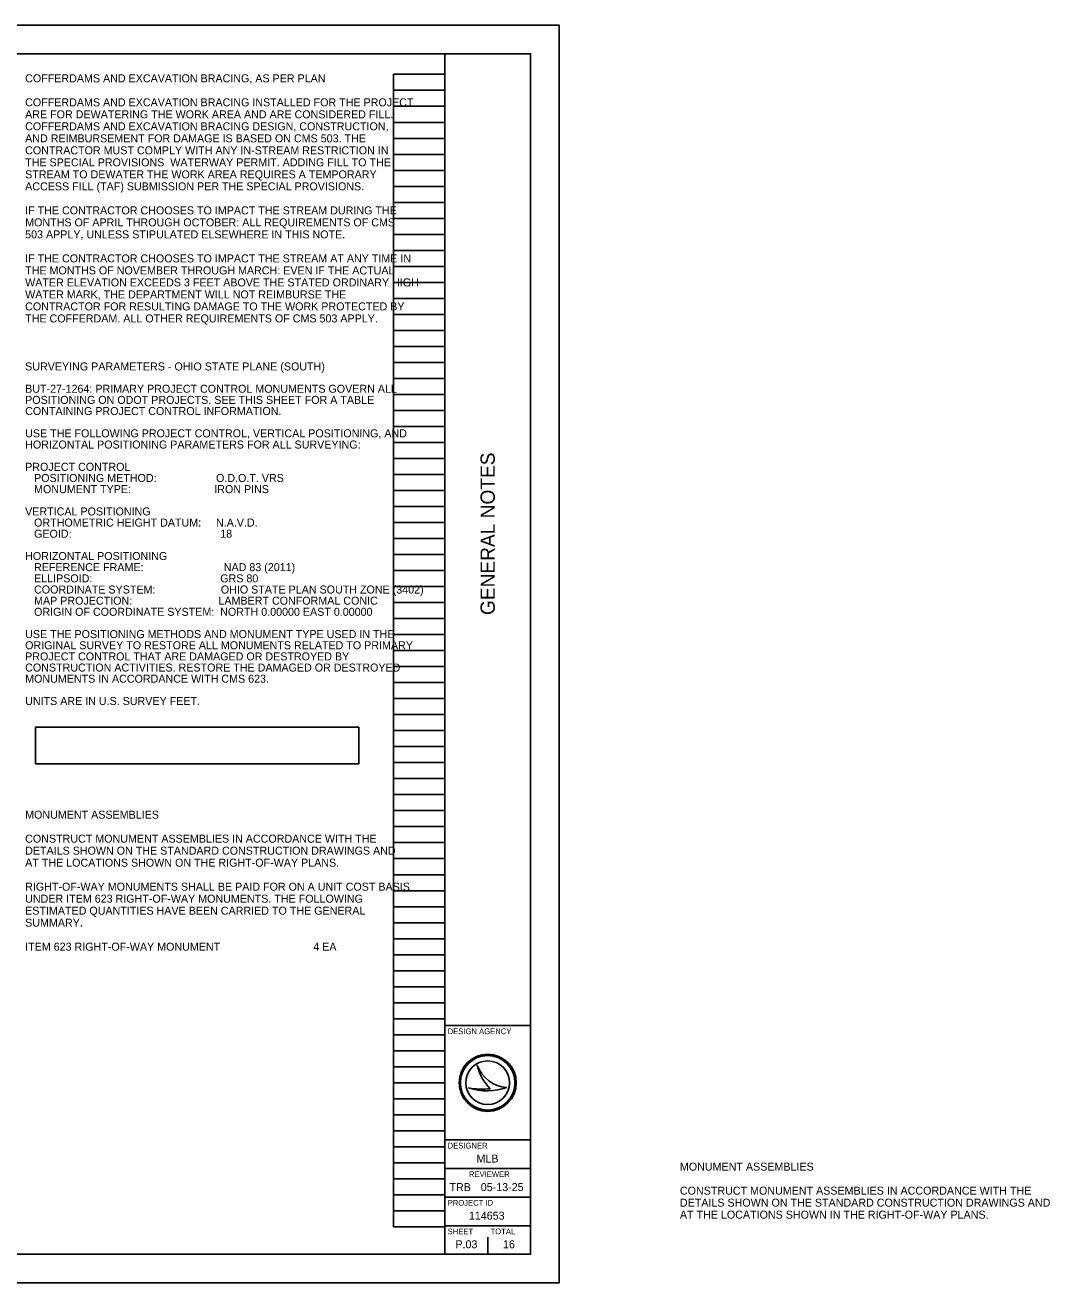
# Model space of a CAD drawing. Extents: x 0 to 42.6, y 0 to 22.
# Drawn here: x 24.66 to 42.58, y 0 to 22 of the extents above; entities that cross this region are included whole.
import ezdxf

# ---------------------------------------------------------------- set-up
doc = ezdxf.new("R2010")
doc.units = 0
for name, color, linetype in [('Default', 7, 'Continuous'), ('SH_Border', 7, 'Continuous'), ('SH_Cut_Line', 7, 'Continuous'), ('SH_Data', 7, 'Continuous'), ('SH_Text', 7, 'Continuous')]:
    doc.layers.add(name, color=color, linetype=linetype)

msp = doc.modelspace()

# ---------------------------------------------------------------- linework, layer by layer
at = {"layer": 'SH_Border'}
for p, q in [((32, 0.5), (32, 21.5)), ((32, 4.5), (33.5, 4.5)), ((32, 2.5), (33.5, 2.5)), ((32, 2), (33.5, 2)), ((32, 1.5), (33.5, 1.5)), ((32, 1), (33.5, 1))]:
    msp.add_line(p, q, dxfattribs=at)
msp.add_lwpolyline([(1.5, 21.5), (33.5, 21.5), (33.5, 0.5), (1.5, 0.5)], close=True, dxfattribs=at)
at = {"layer": 'SH_Cut_Line'}
msp.add_lwpolyline([(0, 0), (34, 0), (34, 22), (0, 22)], close=True, dxfattribs=at)
at = {"layer": 'SH_Data'}
for p, q in [((31.1, 0.98), (31.1, 21.14)), ((31.1, 21.14), (32, 21.14)), ((32, 0.98), (32, 21.14)), ((31.1, 20.86), (32, 20.86)), ((31.1, 20.58), (32, 20.58)), ((31.1, 20.3), (32, 20.3)), ((31.1, 20.02), (32, 20.02)), ((31.1, 19.74), (32, 19.74)), ((31.1, 19.46), (32, 19.46)), ((31.1, 19.18), (32, 19.18)), ((31.1, 18.9), (32, 18.9)), ((31.1, 18.62), (32, 18.62)), ((31.1, 18.34), (32, 18.34)), ((31.1, 18.06), (32, 18.06)), ((31.1, 17.78), (32, 17.78)), ((31.1, 17.5), (32, 17.5)), ((31.1, 17.22), (32, 17.22)), ((31.1, 16.94), (32, 16.94)), ((31.1, 16.66), (32, 16.66)), ((31.1, 16.38), (32, 16.38)), ((31.1, 16.1), (32, 16.1)), ((31.1, 15.82), (32, 15.82)), ((31.1, 15.54), (32, 15.54)), ((31.1, 15.26), (32, 15.26)), ((31.1, 14.98), (32, 14.98)), ((31.1, 14.7), (32, 14.7)), ((31.1, 14.42), (32, 14.42)), ((31.1, 14.14), (32, 14.14)), ((31.1, 13.86), (32, 13.86)), ((31.1, 13.58), (32, 13.58)), ((31.1, 13.3), (32, 13.3)), ((31.1, 13.02), (32, 13.02)), ((31.1, 12.74), (32, 12.74)), ((31.1, 12.46), (32, 12.46)), ((31.1, 12.18), (32, 12.18)), ((31.1, 11.9), (32, 11.9)), ((31.1, 11.62), (32, 11.62)), ((31.1, 11.34), (32, 11.34)), ((31.1, 11.06), (32, 11.06)), ((31.1, 10.78), (32, 10.78)), ((31.1, 10.5), (32, 10.5)), ((31.1, 10.22), (32, 10.22)), ((31.1, 9.94), (32, 9.94)), ((31.1, 9.66), (32, 9.66)), ((31.1, 9.38), (32, 9.38)), ((31.1, 9.1), (32, 9.1)), ((31.1, 8.82), (32, 8.82)), ((31.1, 8.54), (32, 8.54)), ((31.1, 8.26), (32, 8.26)), ((31.1, 7.98), (32, 7.98)), ((31.1, 7.7), (32, 7.7)), ((31.1, 7.42), (32, 7.42)), ((31.1, 7.14), (32, 7.14)), ((31.1, 6.86), (32, 6.86)), ((31.1, 6.58), (32, 6.58)), ((31.1, 6.3), (32, 6.3)), ((31.1, 6.02), (32, 6.02)), ((31.1, 5.74), (32, 5.74)), ((31.1, 5.46), (32, 5.46)), ((31.1, 5.18), (32, 5.18)), ((31.1, 4.9), (32, 4.9)), ((31.1, 4.62), (32, 4.62)), ((31.1, 4.34), (32, 4.34)), ((31.1, 4.06), (32, 4.06)), ((31.1, 3.78), (32, 3.78)), ((32.567, 3.81), (32.567, 3.81)), ((31.1, 3.5), (32, 3.5)), ((32.417, 3.41), (32.417, 3.41)), ((32.75, 3.5), (32.75, 3.5)), ((33.087, 3.419), (33.087, 3.419)), ((31.1, 3.22), (32, 3.22)), ((31.1, 2.94), (32, 2.94)), ((31.1, 2.66), (32, 2.66)), ((31.1, 2.38), (32, 2.38)), ((31.1, 2.1), (32, 2.1)), ((31.1, 1.82), (32, 1.82)), ((31.1, 1.54), (32, 1.54)), ((31.1, 1.26), (32, 1.26)), ((31.1, 0.98), (32, 0.98)), ((32.375, 0.675), (32.375, 0.675)), ((32.75, 0.5), (32.75, 0.8))]:
    msp.add_line(p, q, dxfattribs=at)
for radius in [0.5, 0.477, 0.477, 0.382]:
    msp.add_circle((32.75, 3.5), radius, dxfattribs=at)
for centre, radius, start, end in [((33.116, 3.998), 0.58, 198.9257, 198.9319), ((33.347, 3.97), 0.796, 191.6379, 191.6421), ((33.116, 3.998), 0.58, 198.9319, 267.1657), ((33.347, 3.97), 0.796, 191.6421, 226.0947), ((32.739, 4.37), 1.013, 251.4576, 290.0832), ((32.648, 4.654), 1.266, 259.4964, 259.4995), ((32.739, 4.37), 1.013, 251.4527, 251.4576), ((32.648, 4.654), 1.266, 259.4995, 276.6672)]:
    msp.add_arc(centre, radius, start, end, dxfattribs=at)
at = {"layer": 'SH_Text'}
msp.add_lwpolyline([(24.841, 9.079), (30.498, 9.079), (30.498, 9.72), (24.841, 9.72)], close=True, dxfattribs=at)

# ---------------------------------------------------------------- texts
at = {"layer": 'Default'}
for s, p in [('MONUMENT ASSEMBLIES', (24.66, 8.12)), ('CONSTRUCT MONUMENT ASSEMBLIES IN ACCORDANCE WITH THE ', (24.66, 7.7)), ('DETAILS SHOWN ON THE STANDARD CONSTRUCTION DRAWINGS AND ', (24.66, 7.49)), ('AT THE LOCATIONS SHOWN ON THE RIGHT-OF-WAY PLANS.', (24.66, 7.28)), ('RIGHT-OF-WAY MONUMENTS SHALL BE PAID FOR ON A UNIT COST BASIS ', (24.66, 6.86)), ('UNDER ITEM 623 RIGHT-OF-WAY MONUMENTS. THE FOLLOWING ', (24.66, 6.65)), ('ESTIMATED QUANTITIES HAVE BEEN CARRIED TO THE GENERAL ', (24.66, 6.44)), ('SUMMARY.', (24.66, 6.23)), ('ITEM 623 RIGHT-OF-WAY MONUMENT', (24.66, 5.81)), ('4 EA', (29.7, 5.81))]:
    msp.add_text(s, height=0.14, dxfattribs=at).set_placement(p)
at = {"layer": 'SH_Data'}
msp.add_text('GENERAL NOTES', height=0.25, rotation=90, dxfattribs=at).set_placement((32.875, 11.682))
for s, height, p in [('DESIGN AGENCY', 0.1, (32.05, 4.35)), ('DESIGNER', 0.1, (32.05, 2.35)), ('MLB', 0.14, (32.554, 2.105)), ('REVIEWER', 0.1, (32.422, 1.85)), ('TRB', 0.14, (32.081, 1.605)), ('05-13-25', 0.14, (32.629, 1.605)), ('PROJECT ID', 0.1, (32.05, 1.35)), ('114653', 0.14, (32.421, 1.105)), ('SHEET', 0.1, (32.05, 0.85)), ('TOTAL', 0.1, (32.8, 0.85)), ('P.03', 0.14, (32.185, 0.605)), ('16', 0.14, (33.018, 0.605))]:
    msp.add_text(s, height=height, dxfattribs=at).set_placement(p)
at = {"layer": 'SH_Text'}
for s, p in [('COFFERDAMS AND EXCAVATION BRACING, AS PER PLAN', (24.66, 21)), ('COFFERDAMS AND EXCAVATION BRACING INSTALLED FOR THE PROJECT ', (24.66, 20.58)), ('ARE FOR DEWATERING THE WORK AREA AND ARE CONSIDERED FILL. ', (24.66, 20.37)), ('COFFERDAMS AND EXCAVATION BRACING DESIGN, CONSTRUCTION, ', (24.66, 20.16)), ('AND REIMBURSEMENT FOR DAMAGE IS BASED ON CMS 503. THE ', (24.66, 19.95)), ('CONTRACTOR MUST COMPLY WITH ANY IN-STREAM RESTRICTION IN ', (24.66, 19.74)), ('THE SPECIAL PROVISIONS  WATERWAY PERMIT. ADDING FILL TO THE ', (24.66, 19.53)), ('STREAM TO DEWATER THE WORK AREA REQUIRES A TEMPORARY ', (24.66, 19.32)), ('ACCESS FILL (TAF) SUBMISSION PER THE SPECIAL PROVISIONS. ', (24.66, 19.11)), ('IF THE CONTRACTOR CHOOSES TO IMPACT THE STREAM DURING THE ', (24.66, 18.69)), ('MONTHS OF APRIL THROUGH OCTOBER: ALL REQUIREMENTS OF CMS ', (24.66, 18.48)), ('503 APPLY, UNLESS STIPULATED ELSEWHERE IN THIS NOTE.', (24.66, 18.27)), ('IF THE CONTRACTOR CHOOSES TO IMPACT THE STREAM AT ANY TIME IN ', (24.66, 17.85)), ('THE MONTHS OF NOVEMBER THROUGH MARCH: EVEN IF THE ACTUAL ', (24.66, 17.64)), ('WATER ELEVATION EXCEEDS 3 FEET ABOVE THE STATED ORDINARY HIGH ', (24.66, 17.43)), ('WATER MARK, THE DEPARTMENT WILL NOT REIMBURSE THE ', (24.66, 17.22)), ('THE COFFERDAM. ALL OTHER REQUIREMENTS OF CMS 503 APPLY.', (24.66, 16.8)), ('CONTRACTOR FOR RESULTING DAMAGE TO THE WORK PROTECTED BY ', (24.66, 17.01)), ('SURVEYING PARAMETERS - OHIO STATE PLANE (SOUTH)', (24.66, 15.96)), ('BUT-27-1264: PRIMARY PROJECT CONTROL MONUMENTS GOVERN ALL ', (24.66, 15.57)), ('POSITIONING ON ODOT PROJECTS. SEE THIS SHEET FOR A TABLE ', (24.66, 15.375)), ('CONTAINING PROJECT CONTROL INFORMATION.', (24.66, 15.18)), ('USE THE FOLLOWING PROJECT CONTROL, VERTICAL POSITIONING, AND', (24.66, 14.79)), ('HORIZONTAL POSITIONING PARAMETERS FOR ALL SURVEYING:', (24.66, 14.594)), ('PROJECT CONTROL', (24.66, 14.204)), ('   POSITIONING METHOD:                    O.D.O.T. VRS', (24.66, 14.009)), ('   MONUMENT TYPE:                            IRON PINS', (24.66, 13.814)), ('VERTICAL POSITIONING', (24.66, 13.424)), ('   ORTHOMETRIC HEIGHT DATUM:     N.A.V.D. ', (24.66, 13.229)), ('   GEOID:                                                  18', (24.66, 13.034)), ('HORIZONTAL POSITIONING', (24.66, 12.644)), ('   REFERENCE FRAME:                           NAD 83 (2011)', (24.66, 12.449)), ('   ELLIPSOID:                                           GRS 80', (24.66, 12.253)), ('   COORDINATE SYSTEM:                      OHIO STATE PLAN SOUTH ZONE (3402)', (24.66, 12.058)), ('   MAP PROJECTION:                             LAMBERT CONFORMAL CONIC', (24.66, 11.863)), ('   ORIGIN OF COORDINATE SYSTEM:  NORTH 0.00000 EAST 0.00000', (24.66, 11.668)), ('ORIGINAL SURVEY TO RESTORE ALL MONUMENTS RELATED TO PRIMARY ', (24.66, 11.083)), ('USE THE POSITIONING METHODS AND MONUMENT TYPE USED IN THE ', (24.66, 11.278)), ('PROJECT CONTROL THAT ARE DAMAGED OR DESTROYED BY ', (24.66, 10.888)), ('CONSTRUCTION ACTIVITIES. RESTORE THE DAMAGED OR DESTROYED ', (24.66, 10.693)), ('MONUMENTS IN ACCORDANCE WITH CMS 623.', (24.66, 10.498)), ('UNITS ARE IN U.S. SURVEY FEET.', (24.66, 10.108)), ('MONUMENT ASSEMBLIES', (36.112, 1.963)), ('CONSTRUCT MONUMENT ASSEMBLIES IN ACCORDANCE WITH THE ', (36.112, 1.543)), ('DETAILS SHOWN ON THE STANDARD CONSTRUCTION DRAWINGS AND ', (36.112, 1.333)), ('AT THE LOCATIONS SHOWN IN THE RIGHT-OF-WAY PLANS.', (36.112, 1.123))]:
    msp.add_text(s, height=0.14, dxfattribs=at).set_placement(p)

doc.saveas('drawing.dxf')
